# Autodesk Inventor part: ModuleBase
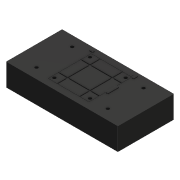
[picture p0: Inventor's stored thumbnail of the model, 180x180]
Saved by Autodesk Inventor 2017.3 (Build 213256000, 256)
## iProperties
Part Number: ModuleBase
Material: ゴム
Document SubType Name: Modeling
Designer: kyushu-hep
Density: 0.93 g/cm^3
Appearance: ゴム - 黒
Mass: 96.9479 g
Surface Area: 172.882 cm^2
Volume: 104.245 cm^3
Author: kyushu-hep
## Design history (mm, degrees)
sketch "スケッチ1"
  geometry: L1 (-50, 25)-(50, 25); L2 (50, 25)-(50, -25); L3 (50, -25)-(-50, -25); L4 (-50, -25)-(-50, 25); 1 further point
  constraints: 8 end point, 2 parallel, 1 horizontal, 1 perpendicular
  dimensions: "d0" = 100 distance of L2.end L3.end; "d1" = 50 distance of L1.end L2.end; "d22" = 25 distance from line of point (0, 0) L3; "d23" = 50 distance from line of L2 point (0, 0)
extrude "押し出し1" new body sketch "スケッチ1" distance "d2" = 20; taper "d3" = 0 deg
sketch "スケッチ4"
  geometry: L1 (17.855, 22.225)-(17.855, 20.225); L2 (17.855, 20.225)-(19.055, 20.225); L3 (19.055, 20.225)-(19.055, 18.225); L4 (19.055, 18.225)-(21.055, 18.225); L5 (21.055, 18.225)-(21.055, 22.225); L6 (21.055, 22.225)-(17.855, 22.225); L7 (21.055, 5)-(21.055, -5); L8 (21.055, -5)-(19.055, -5); L9 (19.055, -5)-(19.055, 5); L10 (19.055, 5)-(21.055, 5); L11 (-50, -25)-(50, -25) reference; L12 (-50, 25)-(-50, -25) reference; L13 (-21.055, 22.225)-(-17.855, 22.225); L14 (-17.855, 22.225)-(-17.855, 20.225); L15 (-17.855, 20.225)-(-21.055, 20.225); L16 (-21.055, 20.225)-(-21.055, 22.225); 1 further point
  constraints: 28 end point, 8 perpendicular, 4 point on line, 2 parallel, 1 collinear, 1 horizontal, 1 vertical
  dimensions: "d12" = 2 distance of L1.start L1.end; "d13" = 1.2 distance of L1.end L2.end; "d14" = 2 distance of L2.end L3.end; "d15" = 2 distance of L3.end L4.end; "d16" = 10 distance of L7.start L7.end; "d24" = 19.055 distance from line of L9 point (0, 0); "d25" = 22.225 distance from line of point (0, 0) L6; "d28" = 17.855 distance from line of point (0, 0) L14
extrude "押し出し4" join sketch "スケッチ4" distance "d29" = 1; taper "d30" = 0 deg
sketch "スケッチ6"
  geometry: L1 (20, 20)-(-20, 20); L2 (-20, 20)-(-20, -20); L3 (-20, -20)-(20, -20); L4 (20, -20)-(20, 20); L5 (20, 20)-(-20, -20); L6 (-20, 20)-(20, -20); C1 r 1.5 at (-32, -16); C2 r 1.5 at (-32, 16); C3 r 1.5 at (-16, -16); C4 r 1.5 at (-16, 16); C5 r 1.5 at (0, -16); C6 r 1.5 at (0, 16); C7 r 1.5 at (16, -16); C8 r 1.5 at (16, 16); C9 r 1.5 at (32, -16); C10 r 1.5 at (32, 16); 1 further point
  constraints: 12 end point, 10 centre point, 2 horizontal, 2 midpoint, 2 parallel, 1 perpendicular, 1 vertical, 18 other
  dimensions: "d41" = 3 diameter of C1; "d42" = 32 horizontal distance of point (0, 0) C1.centre; "d43" = 16 vertical distance of point (0, 0) C1.centre; "d44" = 40 distance of L3.end L2.end; "d45" = 40 distance of L2.end L1.end; "d48" = 32 distance of C1.centre C2.centre; "d51" = 16 distance of C1.centre C3.centre
extrude "押し出し8" cut sketch "スケッチ6" distance "d56" = 20; taper "d57" = 0 deg
sketch "スケッチ7"
  geometry: C1 r 0.5 at (-10, 10); C2 r 0.5 at (10, 10); C3 r 0.5 at (-10, -10); C4 r 0.5 at (10, -10); 1 further point
  constraints: 4 centre point
  dimensions: "d58" = 1 diameter of C1; "d59" = 10 horizontal distance of point (0, 0) C1.centre; "d60" = 10 horizontal distance of point (0, 0) C1.centre; "d61" = 1 diameter of C2; "d62" = 10 horizontal distance of point (0, 0) C2.centre; "d63" = 1 diameter of C3; "d64" = 10 horizontal distance of point (0, 0) C3.centre; "d65" = 1 diameter of C4
extrude "押し出し9" cut sketch "スケッチ7" distance "d66" = 10; taper "d67" = 0 deg
sketch "スケッチ9"
  geometry: L1 (18.5, -19.5)-(-18.5, -19.5); L2 (-18.5, -19.5)-(-18.5, 19.5); L3 (-18.5, 19.5)-(18.5, 19.5); L4 (18.5, 19.5)-(18.5, -19.5); L5 (18.5, -19.5)-(-18.5, 19.5); L6 (-18.5, -19.5)-(18.5, 19.5); L7 (-10.5, 10.5)-(-18, 10.5); L8 (-18, 10.5)-(-18, 19); L9 (-18, 19)-(-10.5, 19); L10 (-10.5, 19)-(-10.5, 10.5); L11 (-10.5, 10.5)-(-18, 19); L12 (-18, 10.5)-(-10.5, 19); L13 (18, 10.5)-(10.5, 10.5); L14 (10.5, 10.5)-(10.5, 19); L15 (10.5, 19)-(18, 19); L16 (18, 19)-(18, 10.5); L17 (-9.5, 19)-(9.5, 19); L18 (9.5, 19)-(9.5, 10.5); L19 (9.5, 10.5)-(-9.5, 10.5); L20 (-9.5, 10.5)-(-9.5, 19); L21 (-18, 9.5)-(-10.5, 9.5); L22 (-10.5, 9.5)-(-10.5, -9.5); L23 (-10.5, -9.5)-(-18, -9.5); L24 (-18, -9.5)-(-18, 9.5); L25 (-18, -10.5)-(-10.5, -10.5); L26 (-10.5, -10.5)-(-10.5, -19); L27 (-10.5, -19)-(-18, -19); L28 (-18, -19)-(-18, -10.5); L29 (-9.5, 9.5)-(9.5, 9.5); L30 (9.5, 9.5)-(9.5, -9.5); L31 (9.5, -9.5)-(-9.5, -9.5); L32 (-9.5, -9.5)-(-9.5, 9.5); L33 (10.5, 9.5)-(18, 9.5); L34 (18, 9.5)-(18, -9.5); L35 (18, -9.5)-(10.5, -9.5); L36 (10.5, -9.5)-(10.5, 9.5); L37 (-9.5, -10.5)-(9.5, -10.5); L38 (9.5, -10.5)-(9.5, -19); L39 (9.5, -19)-(-9.5, -19); L40 (-9.5, -19)-(-9.5, -10.5); L41 (10.5, -10.5)-(18, -10.5); L42 (18, -10.5)-(18, -19); L43 (18, -19)-(10.5, -19); L44 (10.5, -19)-(10.5, -10.5); 2 further points
  constraints: 88 end point, 20 parallel, 19 collinear, 10 horizontal, 10 perpendicular, 4 midpoint, 4 point on line
  dimensions: "d78" = 37 distance of L2.end L3.end; "d79" = 39 distance of L1.end L2.end; "d80" = 7.5 distance of L8.end L9.end; "d81" = 0.5 distance between parallel lines of L3 L9; "d82" = 0.5 distance between parallel lines of L2 L8; "d83" = 8.5 distance of L7.end L8.end; "d88" = 19 distance of L18.end L19.end; "d89" = 8.5 distance of L17.end L18.end; "d90" = 1 distance between parallel lines of L10 L20; "d92" = 19 distance of L21.end L22.end; "d93" = 1 distance between parallel lines of L21 L7; "d94" = 8.5 distance of L25.end L26.end; "d95" = 1 distance between parallel lines of L25 L23; "d96" = 8.5 distance of L13.end L14.end; "d97" = 1 distance between parallel lines of L14 L18
extrude "押し出し11" cut sketch "スケッチ9" distance "d98" = 1; taper "d99" = 0 deg
node "ソリッド1"
